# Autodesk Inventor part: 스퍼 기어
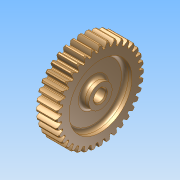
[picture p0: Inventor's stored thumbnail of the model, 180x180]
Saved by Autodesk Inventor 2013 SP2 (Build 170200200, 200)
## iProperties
Created: 2025-10
Part Number: 스퍼 기어
Material: Generic
Document SubType Name: Modeling
Designer: a
Density: 1 g/cm^3
Author: a
변환 표준: STEP AP214IS
전처리기: Build: 200, Release: 2013 SP2 Update 6 - Date: Thu 07/17/2014
전송 단위: 밀리미터
불확실성: 0.01
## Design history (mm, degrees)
node "스퍼 기어1"
node "솔리드1"
node "기준1"
